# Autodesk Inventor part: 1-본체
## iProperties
Created: 2014-12
Part Number: 1-본체
Document SubType Name: Modeling
Designer: Administrator
Density: 2.71 g/cm^3
Material: 알루미늄-6061
Mass: 613.434 g
Surface Area: 665.18 cm^2
Volume: 226.359 cm^3
Author: Administrator
